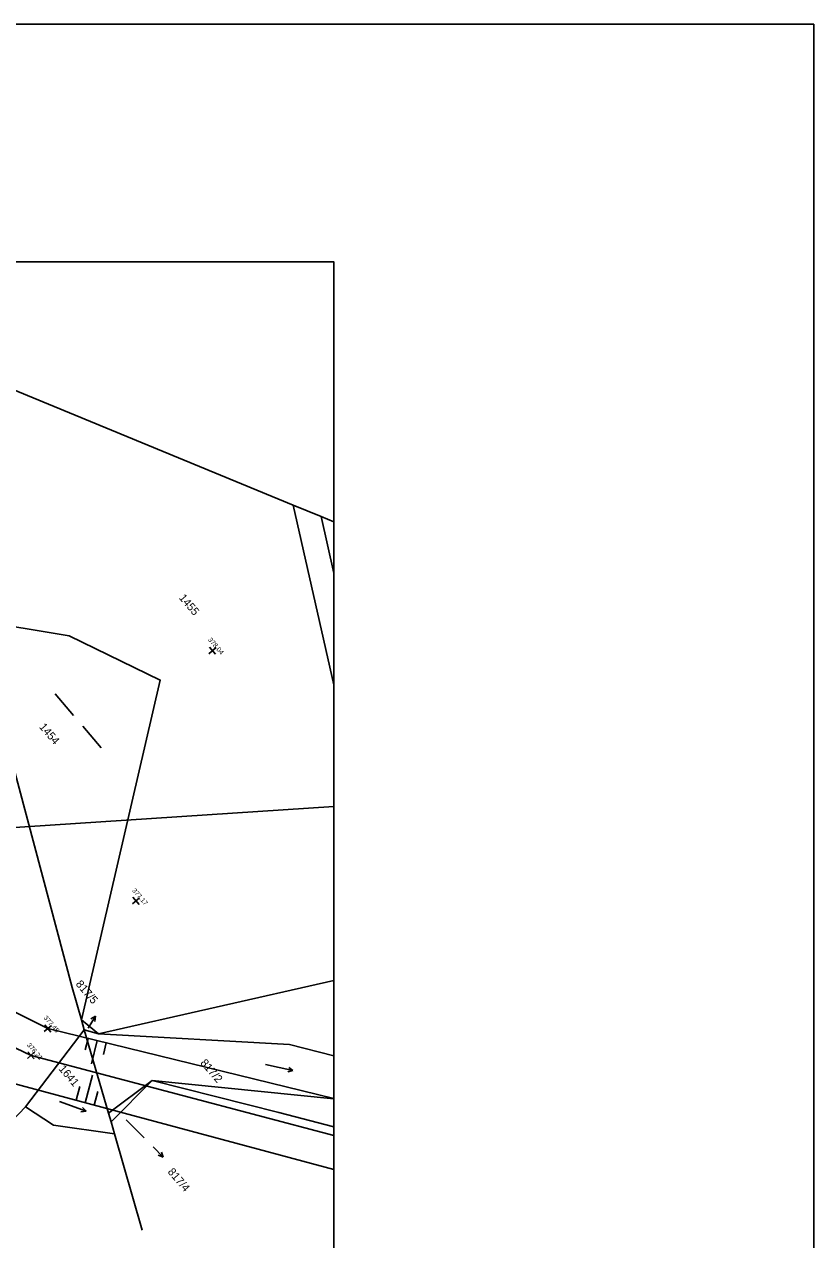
# Model space of a CAD drawing. Extents: x -540141 to -537502, y -1044527 to -1042580.
# Drawn here: x -539596.4 to -539512.6, y -1044017.5 to -1043888.4 of the extents above; entities that cross this region are included whole.
import ezdxf

# ---------------------------------------------------------------- set-up
doc = ezdxf.new("R2010")
doc.units = 0
for name, color, linetype in [('Hranice parcel', 7, 'Continuous'), ('Implicitní', 7, 'Continuous'), ('křížky', 7, 'Continuous'), ('Parcelní čísla', 7, 'Continuous'), ('Pop  PČ popisy', 7, 'Continuous'), ('Vrstva 1', 7, 'Continuous'), ('výšky', 7, 'Continuous'), ('Značky kultur', 7, 'Continuous'), ('ČEZ Spojnice VN', 7, 'Continuous')]:
    doc.layers.add(name, color=color, linetype=linetype)

msp = doc.modelspace()

# ---------------------------------------------------------------- linework, layer by layer
at = {"layer": 'Hranice parcel'}
for p, q in [((-539608.95, -1043922.52), (-539567.86, -1043939.46)), ((-539567.86, -1043939.46), (-539564.9, -1043940.68)), ((-539567.86, -1043939.46), (-539563.54, -1043958.55)), ((-539564.9, -1043940.68), (-539563.54, -1043941.24)), ((-539563.54, -1043946.68), (-539564.9, -1043940.68)), ((-539591.36, -1043990.68), (-539601.74, -1043951.68)), ((-539591.36, -1043990.68), (-539601.74, -1043951.68)), ((-539590.37, -1043994.11), (-539591.36, -1043990.68)), ((-539590.37, -1043994.11), (-539591.36, -1043990.68)), ((-539563.54, -1043989.95), (-539588.56, -1043995.62)), ((-539590.37, -1043994.11), (-539590.06, -1043995.18)), ((-539588.56, -1043995.62), (-539590.37, -1043994.11)), ((-539590.37, -1043994.11), (-539590.06, -1043995.18)), ((-539590.06, -1043995.18), (-539596.32, -1044003.37)), ((-539590.06, -1043995.18), (-539587.49, -1044004.02)), ((-539588.56, -1043995.62), (-539590.06, -1043995.18)), ((-539590.06, -1043995.18), (-539587.49, -1044004.02)), ((-539588.56, -1043995.62), (-539568.25, -1043996.75)), ((-539568.25, -1043996.75), (-539563.54, -1043997.94)), ((-539587.49, -1044004.02), (-539582.85, -1044000.57)), ((-539587.22, -1044004.97), (-539582.85, -1044000.57)), ((-539582.85, -1044000.57), (-539563.54, -1044002.52)), ((-539587.49, -1044004.02), (-539587.22, -1044004.97)), ((-539587.49, -1044004.02), (-539587.22, -1044004.97)), ((-539587.22, -1044004.97), (-539586.86, -1044006.22)), ((-539587.22, -1044004.97), (-539586.86, -1044006.22))]:
    msp.add_line(p, q, dxfattribs=at)
for points in [[(-539590.37, -1043994.11), (-539581.99, -1043958.04), (-539591.67, -1043953.34), (-539601.74, -1043951.68)], [(-539666.5, -1043968.06), (-539621.92, -1044009.02), (-539612.76, -1044016.18), (-539609.59, -1044017.25), (-539596.32, -1044003.37)], [(-539563.54, -1044005.5), (-539569.39, -1044003.98), (-539582.85, -1044000.57)], [(-539596.32, -1044003.37), (-539593.33, -1044005.31), (-539586.86, -1044006.22)], [(-539586.86, -1044006.22), (-539583.9, -1044016.46)]]:
    msp.add_lwpolyline(points, dxfattribs=at)
at = {"layer": 'Implicitní'}
msp.add_line((-539563.54, -1043913.63), (-539566.04, -1043913.63), dxfattribs=at)
for points in [[(-540140.6, -1043888.4), (-539512.56, -1043888.4), (-539512.56, -1044100.69), (-540140.6, -1044100.69)], [(-540058.54, -1043913.63), (-539563.54, -1043913.63), (-539563.54, -1044062.13), (-540058.54, -1044062.13)]]:
    msp.add_lwpolyline(points, close=True, dxfattribs=at)
at = {"layer": 'křížky'}
for p, q in [((-539576.82, -1043955.24), (-539576.06, -1043954.59)), ((-539576.76, -1043954.53), (-539576.11, -1043955.29)), ((-539576.44, -1043954.91), (-539576.44, -1043954.91)), ((-539584.95, -1043981.8), (-539584.19, -1043981.15)), ((-539584.9, -1043981.1), (-539584.24, -1043981.86)), ((-539584.57, -1043981.48), (-539584.57, -1043981.48)), ((-539594.31, -1043995.36), (-539593.55, -1043994.71)), ((-539594.26, -1043994.66), (-539593.61, -1043995.42)), ((-539593.93, -1043995.04), (-539593.93, -1043995.04)), ((-539596.1, -1043998.22), (-539595.35, -1043997.57)), ((-539596.05, -1043997.52), (-539595.4, -1043998.28)), ((-539595.72, -1043997.9), (-539595.72, -1043997.9))]:
    msp.add_line(p, q, dxfattribs=at)
at = {"layer": 'Pop  PČ popisy'}
for p, q in [((-539589.66, -1043995.02), (-539588.88, -1043993.74)), ((-539588.88, -1043993.74), (-539589.35, -1043994.03)), ((-539588.88, -1043993.74), (-539588.93, -1043994.29)), ((-539585.6, -1044004.75), (-539583.68, -1044006.66)), ((-539582.73, -1044007.62), (-539581.67, -1044008.69)), ((-539581.67, -1044008.69), (-539582.2, -1044008.51)), ((-539581.67, -1044008.69), (-539581.85, -1044008.16))]:
    msp.add_line(p, q, dxfattribs=at)
at = {"layer": 'Vrstva 1'}
for p, q in [((-539589.97, -1043997.32), (-539589.66, -1043996.09)), ((-539589.3, -1043998.79), (-539588.69, -1043996.32)), ((-539587.72, -1043996.56), (-539588.02, -1043997.79)), ((-539589.18, -1044000), (-539589.97, -1044002.92)), ((-539590.93, -1044002.66), (-539590.54, -1044001.2)), ((-539588.61, -1044001.72), (-539589, -1044003.18))]:
    msp.add_line(p, q, dxfattribs=at)
for points in [[(-539563.54, -1044002.49), (-539593.93, -1043995.04), (-539629.03, -1043977.47), (-539662.86, -1043959.27), (-539664.22, -1043964.67), (-539666.11, -1043968.56), (-539630.76, -1043982.45), (-539597.7, -1044000.85), (-539563.54, -1044010.01)], [(-539664.22, -1043964.67), (-539629.78, -1043981.67), (-539595.72, -1043997.9), (-539563.54, -1044006.41)]]:
    msp.add_lwpolyline(points, dxfattribs=at)
at = {"layer": 'Značky kultur'}
for p, q in [((-539593.15, -1043959.52), (-539591.19, -1043961.8)), ((-539590.22, -1043962.94), (-539588.26, -1043965.22)), ((-539570.82, -1043998.88), (-539567.89, -1043999.52)), ((-539567.89, -1043999.52), (-539568.42, -1043999.66)), ((-539567.89, -1043999.52), (-539568.31, -1043999.17)), ((-539592.68, -1044002.79), (-539589.87, -1044003.83)), ((-539589.87, -1044003.83), (-539590.42, -1044003.9)), ((-539589.87, -1044003.83), (-539590.24, -1044003.43))]:
    msp.add_line(p, q, dxfattribs=at)
at = {"layer": 'ČEZ Spojnice VN'}
msp.add_lwpolyline([(-539664.76, -1043978.12), (-539563.54, -1043971.45)], dxfattribs=at)

# ---------------------------------------------------------------- texts
at = {"layer": 'Parcelní čísla'}
for s, p in [('1455', (-539580.05, -1043949.34)), ('1454', (-539594.9, -1043963.05)), ('817/5', (-539591.02, -1043990.36)), ('817/2', (-539577.78, -1043998.73)), ('1641', (-539592.83, -1043999.36)), ('817/4', (-539581.25, -1044010.3))]:
    msp.add_text(s, height=0.85, rotation=310.6407, dxfattribs=at).set_placement(p)
at = {"layer": 'výšky'}
for s, p in [('378.04', (-539576.94, -1043953.79)), ('377.17', (-539585.01, -1043980.42)), ('377.45', (-539594.42, -1043993.93)), ('376.21', (-539596.18, -1043996.83))]:
    msp.add_text(s, height=0.5, rotation=310.6406, dxfattribs=at).set_placement(p)

doc.saveas('drawing.dxf')
